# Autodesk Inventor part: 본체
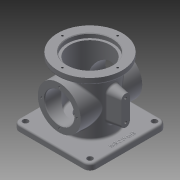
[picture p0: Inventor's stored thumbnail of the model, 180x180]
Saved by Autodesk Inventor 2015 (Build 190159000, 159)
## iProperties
Created: 2017-08
Part Number: 본체
Material: 알루미늄 6061
Document SubType Name: Modeling
Designer: mduedu
Density: 2.71 g/cm^3
Mass: 951.115 g
Surface Area: 966.539 cm^2
Volume: 350.965 cm^3
Appearance: 기본값
Author: mduedu
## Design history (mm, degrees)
sketch "스케치1"
  geometry: L1 (-62.5, -62.5)-(62.5, -62.5); L2 (62.5, -62.5)-(62.5, 62.5); L3 (62.5, 62.5)-(-62.5, 62.5); L4 (-62.5, 62.5)-(-62.5, -62.5); L5 (-62.5, -62.5)-(62.5, 62.5); L6 (62.5, -62.5)-(-62.5, 62.5); 1 further point
  constraints: 12 end point, 2 midpoint, 2 parallel, 1 horizontal, 1 perpendicular
  dimensions: "d232" = 125 distance of L3.end L2.end; "d233" = 125 distance of L2.end L1.end
extrude "돌출1" new body sketch "스케치1" distance "d5" = 10; taper "d6" = 0 deg
sketch "스케치2"
  geometry: C1 r 38 at (0, 0); 1 further point
  constraints: 1 centre point, 1 coincident
  dimensions: "d111" = 76 diameter of C1
extrude "돌출2" join sketch "스케치2" distance "d12" = 88; taper "d13" = 0 deg
sketch "스케치3"
  geometry: C1 r 52.5 at (0, 0); 1 further point
  constraints: 1 centre point, 1 coincident
  dimensions: "d114" = 105 diameter of C1
extrude "돌출3" join sketch "스케치3" distance "d19" = 10; taper "d20" = 0 deg
sketch "스케치4"
  geometry: C1 r 33 at (0, 0); 1 further point
  constraints: 1 centre point, 1 coincident
  dimensions: "d115" = 66 diameter of C1
extrude "돌출4" cut sketch "스케치4" distance "d26" = 86; taper "d27" = 0 deg
sketch "스케치5"
  geometry: C1 r 37 at (0, 0); 1 further point
  constraints: 1 centre point, 1 coincident
  dimensions: "d116" = 74 diameter of C1
extrude "돌출5" cut sketch "스케치5" distance "d29" = 7; taper "d30" = 0 deg
node "작업 평면1"
sketch "스케치18"
  geometry: L1 (-62.5, 0)-(62.5, 0) reference; C1 r 35 at (0, 54); 1 further point
  constraints: 1 centre point, 1 vertical alignment
  dimensions: "d118" = 70 diameter of C1; "d234" = 54 distance from line of C1.centre L1
extrude "돌출9" join sketch "스케치18" stored distance "d120" = 10; taper "d121" = 0 deg
hole "구멍8" diameter "d124" = 48; stored, may be unused: countersink angle "d128" = 90 deg, drill point angle "d130" = 118 deg; dims "d122" = 10, "d123" = 10, "d125" = 6, "d126" = 4, "d127" = 2, "d129" = 8
sketch "스케치9"
  geometry: C1 r 33 at (0, 0); 1 further point
  constraints: 1 centre point, 1 coincident
  dimensions: "d131" = 66 diameter of C1
extrude "돌출8" cut sketch "스케치9" distance "d43" = 16; taper "d44" = 0 deg
node "작업 평면2"
fillet "모깎기9" dims "d137" = 3
fillet "모깎기10" dims "d138" = 3
chamfer "모따기2" distance "d139" = 1; stored, may be unused: second distance "d140" = 2, angle "d141" = 45 deg
fillet "모깎기11" dims "d142" = 3
fillet "모깎기12" dims "d143" = 3
fillet "모깎기13" dims "d144" = 3
node "작업 평면3"
sketch "스케치20"
  geometry: L1 (108, -52.5)-(108, 52.5) reference; L2 (37, 7)-(71, 7); L3 (37, -7)-(71, -7); L4 (0, -33)-(0, 33) reference; A1 r 7 centre (37, 0) between (37, 7) and (37, -7); A2 r 7 centre (71, 0) between (71, 7) and (71, -7); 1 further point
  constraints: 4 end point, 4 point on circle, 3 tangent, 2 centre point, 2 horizontal alignment, 1 parallel, 1 perpendicular
  dimensions: "d203" = 14 diameter of A1; "d206" = 30 distance edge to line of A2 L1; "d207" = 48 dimension on A2 A1 (derived); "d236" = 30 distance edge to line of A1 L4
extrude "돌출10" join sketch "스케치20" stored distance "d152" = 10; taper "d153" = 10 deg
sketch "스케치21"
  geometry: C1 r 7 at (0, 71) reference; C2 r 7 at (0, 37) reference; 3 further points
  constraints: 2 coincident
hole "구멍12" sketch "스케치21" at (0, 71), (0, 37) diameter "d219" = 4.134; stored, may be unused: countersink angle "d223" = 90 deg, drill point angle "d225" = 118 deg; dims "d220" = 6, "d221" = 4, "d222" = 2, "d224" = 8
fillet "모깎기18" dims "d229" = 3
sketch "스케치23"
  geometry: C1 r 20 at (0, 0); 1 further point
  constraints: 1 centre point, 1 coincident
  dimensions: "d168" = 40 diameter of C1
extrude "돌출12" cut sketch "스케치23" stored distance "d169" = 148.25; taper "d170" = 0 deg
sketch "스케치28"
  geometry: L1 (62.5, -62.5)-(62.5, 62.5) reference; 2 further points
  constraints: 1 horizontal alignment, 1 other
  dimensions: "d238" = 10 distance from line of point (52.5, 0) L1
feature "엠보싱4" sketch "스케치28" dims "d239" = 0.5, "d240" = 0
sketch "스케치25" dims "d178" = 58
  geometry: C1 r 35 at (0, 0) reference; 3 further points
  constraints: 2 vertical alignment, 1 coincident, 2 other
hole "구멍10" sketch "스케치25" at (0, 29) diameter "d179" = 3.242; stored, may be unused: countersink angle "d183" = 90 deg, drill point angle "d185" = 118 deg; dims "d180" = 4, "d181" = 4, "d182" = 2, "d184" = 6
sketch "스케치26" dims "d189" = 90
  geometry: 3 further points
  constraints: 2 vertical alignment, 1 coincident, 2 other
hole "구멍11" sketch "스케치26" at (0, 45) diameter "d190" = 3.242; stored, may be unused: countersink angle "d194" = 90 deg, drill point angle "d196" = 118 deg; dims "d191" = 4, "d192" = 4, "d193" = 2, "d195" = 6
chamfer "모따기4" distance "d200" = 1; stored, may be unused: second distance "d201" = 2, angle "d202" = 45 deg
fillet "모깎기19" dims "d241" = 10
sketch "스케치29"
  geometry: A1 r 10 centre (-52.5, 52.5) between (-52.5, 62.5) and (-62.5, 52.5) reference; A2 r 10 centre (52.5, 52.5) between (62.5, 52.5) and (52.5, 62.5) reference; A3 r 10 centre (52.5, -52.5) between (52.5, -62.5) and (62.5, -52.5) reference; A4 r 10 centre (-52.5, -52.5) between (-62.5, -52.5) and (-52.5, -62.5) reference; 5 further points
  constraints: 4 coincident
hole "구멍13" sketch "스케치29" at (-52.5, 52.5), (52.5, 52.5), (52.5, -52.5), (-52.5, -52.5) diameter "d242" = 9; stored, may be unused: countersink angle "d246" = 90 deg, drill point angle "d248" = 118 deg; dims "d243" = 6, "d244" = 4, "d245" = 2, "d247" = 8
fillet "모깎기20" dims "d249" = 3
node "솔리드1"
mirror "대칭2"
pattern_circular "원형 패턴1" dims angle "d187" = 360 deg
mirror "대칭3"
pattern_circular "원형 패턴2" dims angle "d198" = 360 deg
other parameters: "d147" = 58
